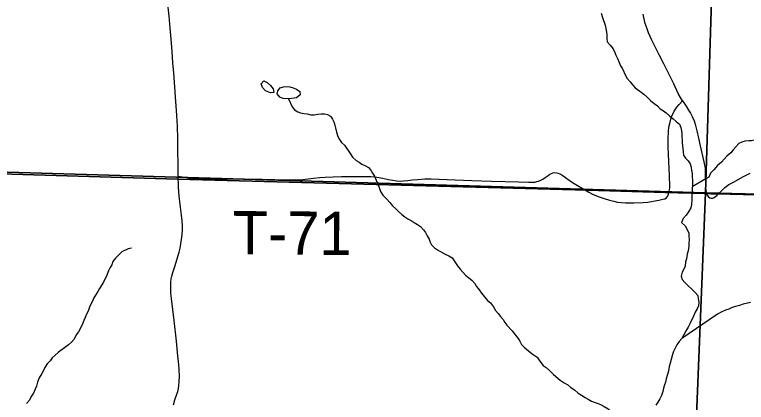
# Model space of a CAD drawing. Extents: x -3.3 to 34, y 0 to 56.8.
# Drawn here: x -2.17 to -1.209, y 33.404 to 33.913 of the extents above; entities that cross this region are included whole.
import ezdxf

# ---------------------------------------------------------------- set-up
doc = ezdxf.new("R2010")
doc.units = 0
for name, color, linetype in [('GM_X_Corporation', 7, 'Continuous'), ('GM_X_County_Road', 7, 'Continuous'), ('GM_X_Township_Road', 7, 'Continuous'), ('GM_X_Township_Road_Text', 7, 'Continuous'), ('GT_Project_Soil_Layers', 7, 'Continuous')]:
    doc.layers.add(name, color=color, linetype=linetype)

msp = doc.modelspace()

# ---------------------------------------------------------------- linework, layer by layer
at = {"layer": 'GM_X_Corporation'}
for points in [[(1.84017, 34.87705), (-3.30393, 34.87705), (-3.30393, 33.7379), (-1.95594, 33.69761), (-1.4178, 33.68276), (-1.31578, 33.67985), (-1.26472, 33.67853), (-1.26192, 33.67846), (-1.25588, 33.6783), (-1.24768, 33.67809), (-0.68402, 33.66353), (0.07113, 33.6404), (0.53861, 33.62974), (1.16908, 33.60969), (1.26798, 33.60697), (1.38132, 33.6045), (1.39386, 33.60423), (1.40335, 33.60404), (1.51565, 33.60182), (1.54523, 33.60124), (1.79797, 33.59224), (1.81648, 34.17132), (1.8337, 34.72257), (1.83943, 34.85654)], [(-2.24907, 34.73274), (-1.23103, 34.70499), (-1.26284, 33.67933), (-2.28281, 33.7097)], [(-1.23103, 34.70499), (-0.21861, 34.67261), (-0.25432, 33.65409), (-1.26284, 33.67933)], [(-2.28281, 33.7097), (-1.26284, 33.67933), (-1.30168, 32.71458), (-2.31978, 32.74649)], [(-1.26284, 33.67933), (-0.25432, 33.65409), (-0.28775, 32.6826), (-1.30168, 32.71458)]]:
    msp.add_lwpolyline(points, close=True, dxfattribs=at)
msp.add_lwpolyline([(0.07113, 33.6404), (-0.68402, 33.66353), (-1.24768, 33.67809), (-1.25588, 33.6783), (-1.26192, 33.67846), (-1.26472, 33.67853), (-1.31578, 33.67985), (-1.4178, 33.68276), (-1.95594, 33.69761), (-3.30393, 33.7379), (-3.30393, 28.07705)], dxfattribs=at)
at = {"layer": 'GM_X_County_Road'}
for points in [[(-1.95519, 33.70152), (-1.95552, 33.75019), (-1.9561, 33.76713), (-1.95688, 33.7811), (-1.95758, 33.7936), (-1.95849, 33.80509), (-1.95955, 33.81859), (-1.96096, 33.8365), (-1.96202, 33.84999), (-1.96315, 33.86495), (-1.96438, 33.88122), (-1.96547, 33.89577), (-1.96699, 33.91128), (-1.96816, 33.92326)], [(-1.96144, 33.40103), (-1.95935, 33.40787), (-1.95685, 33.41537), (-1.95569, 33.41887), (-1.95469, 33.42262), (-1.95402, 33.42653), (-1.95368, 33.43179), (-1.95352, 33.43853), (-1.95385, 33.44803), (-1.95427, 33.45378), (-1.95536, 33.46553), (-1.9571, 33.4847), (-1.96035, 33.51203), (-1.96402, 33.54086), (-1.96469, 33.54778), (-1.96485, 33.55278), (-1.96477, 33.55745), (-1.96469, 33.56236), (-1.96427, 33.5667), (-1.9636, 33.56995), (-1.9621, 33.57469), (-1.95952, 33.58261), (-1.95368, 33.60144), (-1.95244, 33.60702), (-1.95144, 33.61269), (-1.9506, 33.61819), (-1.94994, 33.62427), (-1.94943, 33.63111), (-1.94952, 33.63611), (-1.94985, 33.64261), (-1.95069, 33.64994), (-1.95211, 33.66077), (-1.95327, 33.67144), (-1.95402, 33.68011), (-1.95469, 33.68803), (-1.95519, 33.70152)]]:
    msp.add_lwpolyline(points, dxfattribs=at)
at = {"layer": 'GM_X_Township_Road'}
for points in [[(-1.29307, 33.80004), (-1.29569, 33.8044), (-1.29859, 33.80985), (-1.30445, 33.82235), (-1.31229, 33.83849), (-1.31779, 33.84887), (-1.32375, 33.86052), (-1.33107, 33.87553), (-1.33333, 33.87997), (-1.3356, 33.8847), (-1.33768, 33.88967), (-1.33949, 33.89452), (-1.34191, 33.90192), (-1.34387, 33.9096), (-1.34475, 33.91384)], [(-1.30957, 33.68852), (-1.31021, 33.70155), (-1.31072, 33.71144), (-1.31149, 33.73036), (-1.31174, 33.73982), (-1.312, 33.75006), (-1.31164, 33.76044), (-1.3109, 33.76561), (-1.30989, 33.77051), (-1.30839, 33.77606), (-1.30691, 33.78045), (-1.30556, 33.78358), (-1.30386, 33.78684), (-1.30225, 33.78944), (-1.30033, 33.79186), (-1.29727, 33.79534), (-1.29307, 33.80004), (-1.28809, 33.79303), (-1.28504, 33.78813), (-1.28268, 33.784), (-1.28038, 33.7796), (-1.27787, 33.77393), (-1.27634, 33.76943), (-1.27409, 33.76068), (-1.27191, 33.75104), (-1.2697, 33.74131), (-1.26513, 33.72037), (-1.26355, 33.71179), (-1.26322, 33.70752), (-1.26306, 33.68697)], [(-1.48195, 33.69481), (-1.47889, 33.69609), (-1.47631, 33.69753), (-1.4734, 33.69943), (-1.46964, 33.70211), (-1.46714, 33.70386), (-1.46516, 33.70493), (-1.46311, 33.70565), (-1.46066, 33.70605), (-1.45796, 33.70592), (-1.45612, 33.70547), (-1.45407, 33.70459), (-1.45157, 33.70313), (-1.44496, 33.69846), (-1.43753, 33.6932)], [(-1.23829, 33.68558), (-1.23756, 33.68627), (-1.23589, 33.68776), (-1.23239, 33.69024), (-1.22527, 33.6941), (-1.21383, 33.70029), (-1.20438, 33.7054)], [(-1.95519, 33.70152), (-1.94426, 33.6995), (-1.93915, 33.69882), (-1.93361, 33.69831), (-1.92492, 33.69797), (-1.90846, 33.69776), (-1.89184, 33.69768), (-1.86951, 33.69759), (-1.84487, 33.69731), (-1.82816, 33.69712), (-1.81222, 33.69652), (-1.80549, 33.69643), (-1.79585, 33.69669), (-1.79167, 33.69712), (-1.78443, 33.69805), (-1.77727, 33.69891), (-1.76926, 33.69968), (-1.76235, 33.70019)], [(-1.76235, 33.70019), (-1.7517, 33.70061), (-1.74078, 33.70078), (-1.70217, 33.7007), (-1.6968, 33.70035), (-1.69185, 33.69976), (-1.68623, 33.69865), (-1.67898, 33.69703), (-1.67311, 33.69597), (-1.66831, 33.69527), (-1.66381, 33.69498), (-1.65948, 33.69505), (-1.65375, 33.69549), (-1.64737, 33.69633), (-1.64112, 33.69714), (-1.63585, 33.69758), (-1.63141, 33.69789), (-1.62297, 33.69797), (-1.59143, 33.69669), (-1.56946, 33.69579), (-1.54372, 33.69464), (-1.50832, 33.69385), (-1.49528, 33.69329), (-1.48694, 33.69353), (-1.48419, 33.69413), (-1.48195, 33.69481)], [(-1.43753, 33.6932), (-1.43094, 33.68891), (-1.42351, 33.68462), (-1.41619, 33.68044), (-1.41017, 33.67734), (-1.40247, 33.67423), (-1.39579, 33.67188), (-1.38885, 33.66981), (-1.38341, 33.66843), (-1.3783, 33.66733), (-1.37324, 33.6666), (-1.36797, 33.66628), (-1.36306, 33.66635)], [(-1.36306, 33.66635), (-1.35718, 33.66643), (-1.3449, 33.66686), (-1.33869, 33.66732), (-1.33181, 33.66833), (-1.32414, 33.6697), (-1.31889, 33.67099), (-1.31641, 33.67178), (-1.3143, 33.67295), (-1.31259, 33.67478), (-1.31138, 33.6777), (-1.31044, 33.68209), (-1.30992, 33.68554), (-1.30957, 33.68852)], [(-1.26306, 33.68697), (-1.26257, 33.68269), (-1.26161, 33.67916), (-1.26057, 33.67655), (-1.25895, 33.67406), (-1.25731, 33.67275), (-1.25533, 33.67226), (-1.2532, 33.67242), (-1.2514, 33.67321), (-1.24794, 33.67611), (-1.24046, 33.68351), (-1.23829, 33.68558)]]:
    msp.add_lwpolyline(points, dxfattribs=at)
at = {"layer": 'GT_Project_Soil_Layers'}
for points in [[(-1.39996, 33.91521), (-1.39799, 33.90954), (-1.39481, 33.89933), (-1.39321, 33.8929), (-1.39237, 33.88722), (-1.3923, 33.8819), (-1.39186, 33.87773), (-1.38801, 33.87323), (-1.38415, 33.86835), (-1.38182, 33.86382), (-1.38063, 33.86004), (-1.3783, 33.8559), (-1.37633, 33.85061), (-1.37437, 33.84608), (-1.37204, 33.84232), (-1.36775, 33.83327), (-1.3658, 33.8295), (-1.36195, 33.82499), (-1.35848, 33.82087), (-1.35502, 33.81712), (-1.34927, 33.81302), (-1.34391, 33.80892), (-1.33968, 33.80518), (-1.33507, 33.80069), (-1.33047, 33.79658), (-1.32588, 33.7936), (-1.32241, 33.78985), (-1.31821, 33.78725), (-1.31437, 33.78427), (-1.31015, 33.78053), (-1.30517, 33.7768), (-1.30133, 33.77306), (-1.29711, 33.7697), (-1.29515, 33.76517), (-1.29433, 33.76063), (-1.2939, 33.75684), (-1.29384, 33.75266), (-1.29342, 33.74887), (-1.29336, 33.74507), (-1.29293, 33.74128), (-1.29206, 33.73332), (-1.29162, 33.72877), (-1.2893, 33.725), (-1.28583, 33.72126), (-1.28313, 33.7175), (-1.28193, 33.71296), (-1.28111, 33.70879), (-1.2803, 33.70501), (-1.28024, 33.70083), (-1.27979, 33.69552), (-1.2801, 33.6902), (-1.2804, 33.68412), (-1.28034, 33.67994), (-1.28065, 33.675), (-1.28097, 33.67044), (-1.28126, 33.66436), (-1.28234, 33.65979), (-1.2853, 33.65443), (-1.28827, 33.65021), (-1.29238, 33.6456), (-1.29421, 33.64064), (-1.2896, 33.63615), (-1.28688, 33.63125), (-1.28492, 33.62634), (-1.28486, 33.62254), (-1.28442, 33.61799), (-1.28473, 33.61305), (-1.28468, 33.60925), (-1.28574, 33.60354), (-1.28681, 33.59897), (-1.28787, 33.59288), (-1.28895, 33.58907), (-1.28963, 33.58336), (-1.29147, 33.57916), (-1.2937, 33.57533), (-1.29476, 33.57), (-1.29356, 33.56584), (-1.2901, 33.56171), (-1.27665, 33.5486), (-1.27318, 33.54485), (-1.27274, 33.5403), (-1.27154, 33.53576), (-1.27224, 33.5312), (-1.2737, 33.52738), (-1.27629, 33.52279), (-1.27887, 33.51743), (-1.28329, 33.5075), (-1.2855, 33.50329), (-1.28809, 33.4987), (-1.29106, 33.4941), (-1.29402, 33.48836)], [(-1.83385, 33.81087), (-1.84033, 33.81344), (-1.84456, 33.81793), (-1.84614, 33.82247), (-1.84278, 33.82631), (-1.8382, 33.8241), (-1.83398, 33.82036), (-1.8305, 33.81585), (-1.82968, 33.8113), (-1.83385, 33.81087)], [(-1.81706, 33.80313), (-1.82163, 33.80496), (-1.82511, 33.80947), (-1.8244, 33.81328), (-1.82142, 33.81711), (-1.81689, 33.81869), (-1.81311, 33.81913), (-1.80855, 33.81843), (-1.80398, 33.81735), (-1.79978, 33.81551), (-1.79557, 33.81253), (-1.79513, 33.80798), (-1.79963, 33.80412), (-1.80929, 33.80292), (-1.81706, 33.80313)], [(-1.81043, 33.80295), (-1.80554, 33.79227), (-1.80245, 33.78852), (-1.79824, 33.78592), (-1.79443, 33.78445), (-1.79025, 33.78375), (-1.78569, 33.78305), (-1.78113, 33.78198), (-1.77658, 33.78204), (-1.77204, 33.78286), (-1.76749, 33.78331), (-1.76294, 33.78337), (-1.75914, 33.78228), (-1.75531, 33.78006), (-1.75261, 33.7763), (-1.75066, 33.77253), (-1.74947, 33.76837), (-1.74866, 33.76458), (-1.74745, 33.75928), (-1.74547, 33.75361), (-1.74352, 33.74946), (-1.74081, 33.74571), (-1.73697, 33.74196), (-1.72924, 33.73106), (-1.72614, 33.72616), (-1.72153, 33.72205), (-1.71771, 33.71982), (-1.71388, 33.71722), (-1.7093, 33.715), (-1.70548, 33.71278), (-1.70239, 33.70902), (-1.70007, 33.70526), (-1.69736, 33.7015), (-1.69423, 33.69395), (-1.69265, 33.68979), (-1.69069, 33.68526), (-1.6895, 33.6811), (-1.6864, 33.67621), (-1.68179, 33.67172), (-1.67717, 33.66684), (-1.6737, 33.66233), (-1.66948, 33.6586), (-1.66601, 33.65485), (-1.66141, 33.65111), (-1.65758, 33.64813), (-1.65375, 33.64552), (-1.64916, 33.64293), (-1.64534, 33.6407), (-1.64075, 33.63773), (-1.63692, 33.63512), (-1.63307, 33.631), (-1.63037, 33.62724), (-1.62804, 33.62309), (-1.6257, 33.61857), (-1.62451, 33.61479), (-1.62256, 33.61102), (-1.61872, 33.60727), (-1.61451, 33.60467), (-1.60878, 33.60134), (-1.60458, 33.59912), (-1.59962, 33.59691), (-1.59541, 33.59393), (-1.58844, 33.58377), (-1.58497, 33.57926), (-1.5815, 33.57513), (-1.57803, 33.57138), (-1.57344, 33.56803), (-1.5696, 33.56466), (-1.56575, 33.56054), (-1.56342, 33.55639), (-1.55995, 33.55227), (-1.55685, 33.54775), (-1.55338, 33.54324), (-1.54875, 33.53761), (-1.54492, 33.53501), (-1.54106, 33.52974), (-1.53834, 33.52522), (-1.53525, 33.52109), (-1.53178, 33.51696), (-1.5287, 33.51321), (-1.52637, 33.50944), (-1.52367, 33.50568), (-1.51674, 33.49818), (-1.51249, 33.49254), (-1.50902, 33.48841), (-1.5067, 33.48465), (-1.50436, 33.4805), (-1.5009, 33.47675), (-1.49515, 33.47228), (-1.49054, 33.46816), (-1.48404, 33.46369), (-1.48017, 33.45843), (-1.47592, 33.45279), (-1.47209, 33.45019), (-1.46787, 33.44645), (-1.46249, 33.44121), (-1.45366, 33.43335), (-1.44831, 33.43001), (-1.44372, 33.42742), (-1.4395, 33.42406), (-1.43491, 33.4207)], [(-1.17833, 33.76301), (-1.1821, 33.76105), (-1.18545, 33.75645), (-1.18921, 33.75412), (-1.1937, 33.74988), (-1.19748, 33.74907), (-1.2024, 33.74786), (-1.20619, 33.74781), (-1.21149, 33.74735), (-1.21527, 33.74616), (-1.21903, 33.74421), (-1.22314, 33.73998), (-1.2265, 33.73575), (-1.22986, 33.73191), (-1.23473, 33.72767), (-1.24182, 33.71959), (-1.24707, 33.71534), (-1.25192, 33.70958), (-1.25642, 33.70534), (-1.25862, 33.69999), (-1.26238, 33.69766), (-1.28024, 33.68722)], [(-2.01649, 33.60673), (-2.02065, 33.60591), (-2.02894, 33.602), (-2.03755, 33.59391), (-2.0409, 33.58931), (-2.04235, 33.58511), (-2.0442, 33.58128), (-2.04642, 33.57708), (-2.04861, 33.57135), (-2.05304, 33.56218), (-2.05823, 33.55375), (-2.06045, 33.54992), (-2.06565, 33.5415), (-2.06749, 33.53729), (-2.06971, 33.53347), (-2.07155, 33.52926), (-2.07337, 33.52392), (-2.07559, 33.52009), (-2.07705, 33.5159), (-2.07889, 33.51169), (-2.08109, 33.50635), (-2.0859, 33.49717), (-2.08887, 33.49295), (-2.09183, 33.48759), (-2.09519, 33.48337), (-2.09893, 33.4799), (-2.11244, 33.46984), (-2.12069, 33.46289), (-2.12329, 33.45905), (-2.12703, 33.45482), (-2.13, 33.45023), (-2.13184, 33.4464), (-2.13406, 33.4422), (-2.1374, 33.43683), (-2.13959, 33.43073), (-2.14104, 33.42577), (-2.14288, 33.42194), (-2.14508, 33.4166), (-2.14805, 33.412), (-2.15026, 33.40741), (-2.15437, 33.4028)], [(-1.20366, 33.53557), (-1.21349, 33.53316), (-1.2184, 33.53157), (-1.22331, 33.53036), (-1.22784, 33.52878), (-1.23236, 33.52682), (-1.23651, 33.52524), (-1.24217, 33.52288), (-1.24706, 33.52016), (-1.29402, 33.48836)], [(-1.29402, 33.48836), (-1.29738, 33.48414), (-1.30035, 33.47992), (-1.30257, 33.47571), (-1.30478, 33.47112), (-1.30624, 33.4673), (-1.30912, 33.45587), (-1.31058, 33.45129), (-1.31163, 33.44558), (-1.31307, 33.43948), (-1.31453, 33.43529), (-1.31523, 33.4311), (-1.31669, 33.42728), (-1.31815, 33.42308), (-1.31885, 33.41852), (-1.32067, 33.41355), (-1.32289, 33.40896), (-1.32548, 33.40475), (-1.32809, 33.40092)], [(-1.43491, 33.4207), (-1.42992, 33.41659), (-1.42572, 33.41399), (-1.42075, 33.41102), (-1.41692, 33.40842), (-1.41234, 33.4062), (-1.40776, 33.40437), (-1.40395, 33.4029), (-1.39975, 33.40106), (-1.39593, 33.39884), (-1.39058, 33.39587), (-1.38598, 33.39214), (-1.38138, 33.38878), (-1.3764, 33.38467), (-1.37293, 33.38055), (-1.37022, 33.37679), (-1.36713, 33.37265), (-1.36292, 33.36967), (-1.35835, 33.36821), (-1.35379, 33.36752)]]:
    msp.add_lwpolyline(points, dxfattribs=at)

# ---------------------------------------------------------------- texts
at = {"layer": 'GM_X_Township_Road_Text'}
msp.add_text('T-71', height=0.056818, rotation=359.64342, dxfattribs=at).set_placement((-1.88375, 33.59877))

doc.saveas('drawing.dxf')
